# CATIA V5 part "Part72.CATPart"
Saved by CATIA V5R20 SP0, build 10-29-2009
Part number: FA 053000-3
Revision: ANY
Definition: UNKNOWN
Nomenclature: FA 053000-3
Source: Unknown
Bounding box of the stored display mesh (mm): x 0 to 2, y -1.45 to 1.45, z -1.45 to 1.45
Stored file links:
  C:\Users\Utente\Desktop\IO LAVORO\3D X SITO CF\CUMSA\3D files FA\FA 053004-20\Part72.CATPart

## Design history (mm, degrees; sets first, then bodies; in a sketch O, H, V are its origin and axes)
Body1 "Revolución1" (main body)
  Solid1: solid without history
